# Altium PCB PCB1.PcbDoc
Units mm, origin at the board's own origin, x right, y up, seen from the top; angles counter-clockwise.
Board outline 25 x 17 mm, 2 copper layers (Top Layer, Bottom Layer); 9 components, 6 nets, 20 pads, 2 vias.
Unrouted connection lines stored in the file: 1.
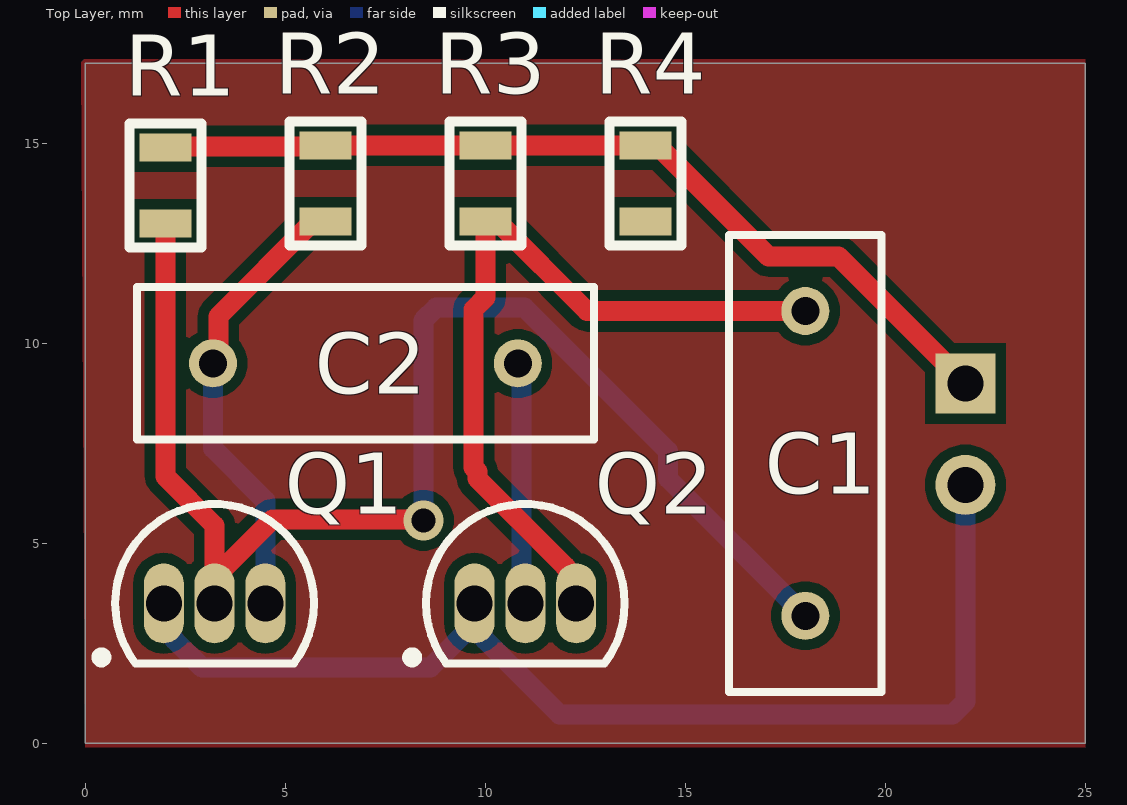
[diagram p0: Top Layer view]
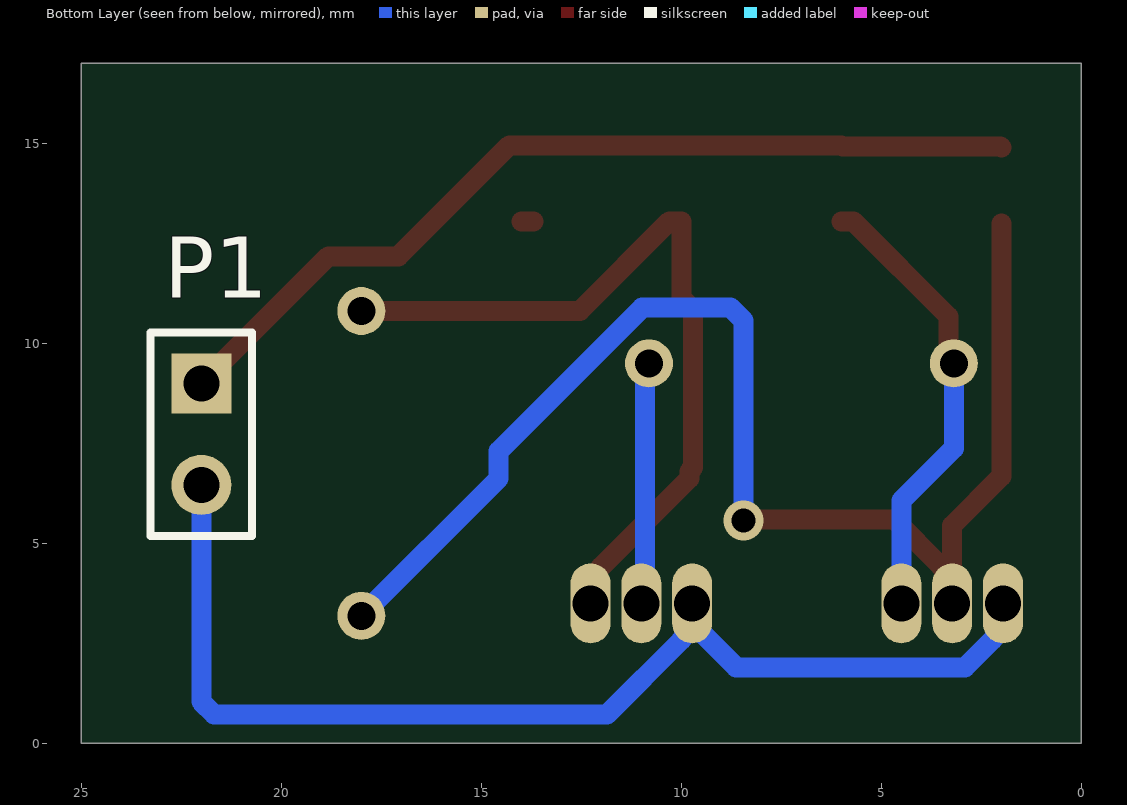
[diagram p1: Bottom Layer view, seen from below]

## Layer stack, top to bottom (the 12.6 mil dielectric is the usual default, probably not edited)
Top Solder: solder mask 0.0102, Solder Resist, Dk 3.5
Top Layer: signal copper 0.0356
Dielectric 1: dielectric 0.32, FR-4, Dk 4.8
Bottom Layer: signal copper 0.0356
Bottom Solder: solder mask 0.0102, Solder Resist, Dk 3.5

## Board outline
0,0 25,0 25,17 0,17

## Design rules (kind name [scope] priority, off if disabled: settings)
Clearance [All] p1: gap=0.254 ignorepadtopadclearanceinfootprint=FALSE except(0.3: Arc-Arc Arc-Track Track-Track)
PolygonConnect [All] p1: connectstyle=Relief reliefconductorwidth=0.254 reliefentries=4 polygonreliefangle="90 Angle" airgapwidth=0.254
RoutingVias [All] p1: holewidth=0.6 width=1 viastyle="Through Hole" minholewidth=0.4 minwidth=0.7 maxholewidth=0.711 maxwidth=1.27
SolderMaskExpansion [All] p1: expansion=0.102 istentingtop=FALSE
Width [All] p1: maxlimit=1 minlimit=0.1 preferedwidth=0.254
30 further rules are at their usual default settings.

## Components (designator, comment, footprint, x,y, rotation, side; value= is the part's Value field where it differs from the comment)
C1 "Cap" RAD-0.3 18,7 r90 top value=100pF
C2 "Cap" RAD-0.3 7,9.5 r0 top value=100pF
P1 "Header 2" HDR1X2 22,9 r270 bottom
Q1 "2N3904" TO-92A 3.23,3.5 r270 top
Q2 "2N3904" TO-92A 11,3.5 r270 top
R1 "Res" "Res 0805" 2,13.95 r90 top
R2 "Res" "Res 0805" 6,14 r90 top
R3 "Res" "Res 0805" 10,14 r90 top
R4 "Res" "Res 0805" 14,14 r90 top

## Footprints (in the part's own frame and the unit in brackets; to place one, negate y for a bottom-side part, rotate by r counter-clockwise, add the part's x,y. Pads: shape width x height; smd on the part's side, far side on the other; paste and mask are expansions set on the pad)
HDR1X2 [mm] "Connector; Header; 2 Position"
  rect 1.5x1.5 hole 0.9: 1(0,0)
  round 1.5 hole 0.9: 2(2.54,0)
  silkscreen extent -1.27,-1.27 3.81,1.27
RAD-0.3 [mm] "Radial Cap, Thru-Hole; 2 Leads; 0.3 in Pin Spacing"
  round 1.2 hole 0.7: 1(-3.81,0) 2(3.81,0)
  silkscreen extent -5.71,-1.91 5.71,1.91
"Res 0805" [mm]
  rect 0.7x1.3 smd: 1(-0.95,0) 2(0.95,0)
  silkscreen extent -1.55,-0.9 1.55,0.9
TO-92A [mm] "TO, Flat Index; 3 In-Line, Axial Leads; Body Dia. 4.5mm; Leads 0.51 x 0.48 mm (max)"
  oval 2x1 hole 0.9: 1(0,-1.27) 2(0,0) 3(0,1.27)
  silkscreen extent -2.48,-2.95 1.5,2.48, body extent -2.48,-2.5 1.5,2.5, height 6.86

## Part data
C1 C2: "Capacitor"
P1: "Header, 2-Pin"
Q1 Q2: "NPN General Purpose Amplifier"

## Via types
v1: diameter 1, hole 0.6, Top Layer to Bottom Layer, 2 vias

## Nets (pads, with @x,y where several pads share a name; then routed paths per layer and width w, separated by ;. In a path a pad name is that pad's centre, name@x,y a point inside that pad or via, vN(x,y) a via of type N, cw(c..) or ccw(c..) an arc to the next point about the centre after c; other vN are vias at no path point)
+12V: P1.1 R1.2 R2.2 R3.2 R4.2 | length 22.5
  Top Layer w0.5: R1.2 2.025,14.925 5.975,14.925 R2.2 R3.2 R4.2 14.3,14.95 17.075,12.175 18.825,12.175 P1.1
GND: P1.2 Q1.1 Q2.1 | length 29.1
  Bottom Layer w0.5: Q1.1 1.96,2.865 2.226,2.599 2.226,2.584 2.91,1.9 8.63,1.9 9.73,3 Q2.1 9.73,2.865 9.996,2.599 9.996,2.584 11.855,0.725 21.682,0.725 22,1.043 P1.2
NetC1_1: C1.1 Q1.2 R1.1 | length 34.1
  Top Layer w0.5: R1.1 2,6.675 3.23,5.445 Q1.2@3.23,4.135 ; Q1.2 Q1.2@3.23,4.135 ; v1(8.45,5.575) 8.425,5.6 4.68,5.6 3.496,4.416 3.496,4.401 Q1.2@3.23,4.135
  Bottom Layer w0.5: v1(8.45,5.575) 8.45,10.575 8.768,10.893 10.978,10.893 14.567,7.305 14.567,6.623 v1(18,3.19)
NetC1_2: C1.2 Q2.3 R3.1 | length 19.7
  Top Layer w0.5: Q2.3 12.27,4.135 12.004,4.401 12.004,4.416 9.8,6.62 9.8,6.8 9.706,6.894 9.706,10.849 10,11.143 R3.1 10.3,13.05 12.54,10.81 C1.2
NetC2_1: C2.1 Q1.3 R2.1 | length 11.4
  Top Layer w0.5: C2.1 3.324,9.634 3.324,10.674 5.7,13.05 R2.1
  Bottom Layer w0.5: C2.1 3.19,7.378 4.5,6.068 Q1.3
NetC2_2: C2.2 Q2.2 R4.1 | length 6.4
  Top Layer w0.5: R4.1@13.7,13.05 R4.1
  Bottom Layer w0.5: C2.2 10.905,9.405 10.905,3.595 Q2.2

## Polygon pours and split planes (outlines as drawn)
no net on Top Layer "NONET_L01_P000" (solid, pour order 0): -0.1,17.1 25,17.1 25,-0.1 0,-0.1

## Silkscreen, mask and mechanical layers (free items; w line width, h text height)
Mechanical 1:
  the board outline again, w0.254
